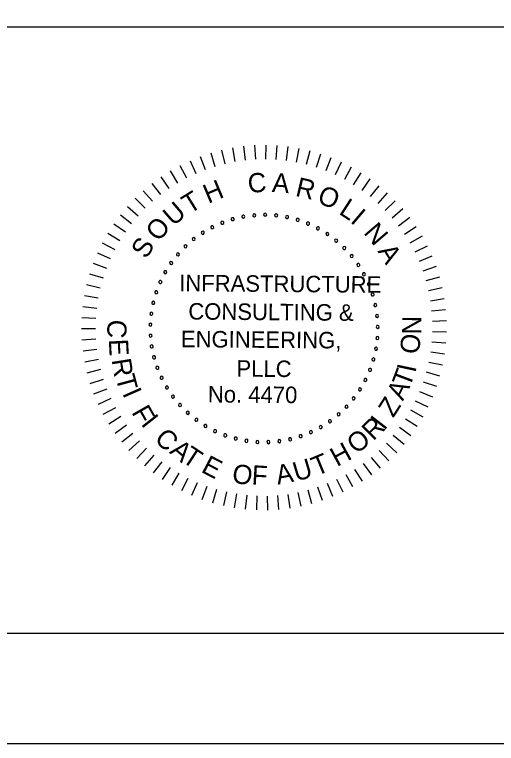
# Model space of a CAD drawing. Extents: x -305 to -161, y -187 to -99.
# Drawn here: x -204.37 to -195.63, y -187.49 to -174.27 of the extents above; entities that cross this region are included whole.
import ezdxf

# ---------------------------------------------------------------- set-up
doc = ezdxf.new("R2010")
doc.units = 0
for name, color, linetype in [('BR_BORDER LINES', 7, 'Continuous'), ('BR_TEXT', 7, 'Continuous'), ('Level 31', 7, 'Continuous')]:
    doc.layers.add(name, color=color, linetype=linetype)

msp = doc.modelspace()

# ---------------------------------------------------------------- linework, layer by layer
at = {"layer": 'BR_BORDER LINES'}
for p, q in [((-214.64, -174.489), (-193.18, -174.489)), ((-297.843, -185.489), (-163.178, -185.489))]:
    msp.add_line(p, q, dxfattribs=at)
at = {"layer": 'BR_TEXT'}
for p, q in [((-200.615, -176.726), (-200.555, -176.974)), ((-200.417, -176.685), (-200.373, -176.936)), ((-200.217, -176.656), (-200.188, -176.909)), ((-200.016, -176.64), (-200.002, -176.894)), ((-199.814, -176.636), (-199.816, -176.89)), ((-199.612, -176.644), (-199.63, -176.898)), ((-199.411, -176.664), (-199.444, -176.917)), ((-199.212, -176.697), (-199.26, -176.947)), ((-199.015, -176.741), (-199.079, -176.988)), ((-201.001, -176.844), (-200.912, -177.082)), ((-200.81, -176.779), (-200.735, -177.023)), ((-198.821, -176.798), (-198.9, -177.04)), ((-198.631, -176.866), (-198.724, -177.103)), ((-201.37, -177.007), (-201.252, -177.233)), ((-201.188, -176.92), (-201.084, -177.153)), ((-198.446, -176.946), (-198.553, -177.177)), ((-201.546, -177.106), (-201.415, -177.324)), ((-198.265, -177.037), (-198.387, -177.261)), ((-198.091, -177.139), (-198.226, -177.355)), ((-201.716, -177.215), (-201.572, -177.425)), ((-197.923, -177.251), (-198.071, -177.458)), ((-201.879, -177.334), (-201.723, -177.535)), ((-197.762, -177.373), (-197.922, -177.571)), ((-202.035, -177.463), (-201.866, -177.654)), ((-197.609, -177.505), (-197.781, -177.693)), ((-202.182, -177.601), (-202.002, -177.781)), ((-197.464, -177.646), (-197.647, -177.823)), ((-202.321, -177.748), (-202.13, -177.917)), ((-197.329, -177.795), (-197.522, -177.961)), ((-202.45, -177.903), (-202.25, -178.06)), ((-202.57, -178.065), (-202.36, -178.21)), ((-197.202, -177.952), (-197.405, -178.106)), ((-197.086, -178.117), (-197.298, -178.258)), ((-202.679, -178.235), (-202.461, -178.366)), ((-196.979, -178.289), (-197.199, -178.417)), ((-202.779, -178.411), (-202.553, -178.529)), ((-196.883, -178.467), (-197.111, -178.581)), ((-202.867, -178.593), (-202.634, -178.696)), ((-196.799, -178.65), (-197.033, -178.75)), ((-202.944, -178.779), (-202.705, -178.869)), ((-196.725, -178.838), (-196.965, -178.924)), ((-203.009, -178.97), (-202.766, -179.045)), ((-196.664, -179.03), (-196.908, -179.101)), ((-203.063, -179.165), (-202.815, -179.225)), ((-196.614, -179.226), (-196.862, -179.282)), ((-203.104, -179.363), (-202.853, -179.407)), ((-196.576, -179.424), (-196.827, -179.465)), ((-203.134, -179.562), (-202.881, -179.592)), ((-196.55, -179.625), (-196.804, -179.65)), ((-203.151, -179.764), (-202.897, -179.777)), ((-196.537, -179.826), (-196.791, -179.836)), ((-203.156, -179.965), (-202.901, -179.964)), ((-196.535, -180.028), (-196.79, -180.022)), ((-203.149, -180.167), (-202.895, -180.15)), ((-196.547, -180.23), (-196.8, -180.208)), ((-203.129, -180.368), (-202.877, -180.335)), ((-196.57, -180.43), (-196.822, -180.393)), ((-203.097, -180.568), (-202.847, -180.52)), ((-196.606, -180.629), (-196.855, -180.577)), ((-203.053, -180.765), (-202.807, -180.701)), ((-196.653, -180.825), (-196.899, -180.758)), ((-202.997, -180.959), (-202.755, -180.881)), ((-196.713, -181.018), (-196.954, -180.936)), ((-202.93, -181.149), (-202.693, -181.056)), ((-196.784, -181.207), (-197.02, -181.111)), ((-202.851, -181.335), (-202.62, -181.228)), ((-196.867, -181.392), (-197.096, -181.281)), ((-202.761, -181.516), (-202.536, -181.395)), ((-196.96, -181.57), (-197.182, -181.446)), ((-202.66, -181.69), (-202.443, -181.556)), ((-197.065, -181.743), (-197.279, -181.605)), ((-202.548, -181.859), (-202.34, -181.711)), ((-197.179, -181.91), (-197.385, -181.759)), ((-202.426, -182.02), (-202.228, -181.86)), ((-197.304, -182.068), (-197.5, -181.905)), ((-202.295, -182.173), (-202.107, -182.002)), ((-202.155, -182.319), (-201.977, -182.136)), ((-197.438, -182.219), (-197.623, -182.045)), ((-202.006, -182.455), (-201.84, -182.262)), ((-197.733, -182.495), (-197.895, -182.3)), ((-197.581, -182.362), (-197.756, -182.176)), ((-201.849, -182.582), (-201.695, -182.379)), ((-197.892, -182.62), (-198.042, -182.414)), ((-201.685, -182.699), (-201.543, -182.487)), ((-198.059, -182.734), (-198.196, -182.519)), ((-201.513, -182.806), (-201.385, -182.586)), ((-201.336, -182.903), (-201.221, -182.675)), ((-198.411, -182.93), (-198.522, -182.701)), ((-198.232, -182.837), (-198.356, -182.615)), ((-201.153, -182.988), (-201.053, -182.754)), ((-200.965, -183.062), (-200.879, -182.822)), ((-198.596, -183.012), (-198.692, -182.777)), ((-200.773, -183.125), (-200.702, -182.88)), ((-200.577, -183.175), (-200.521, -182.927)), ((-200.379, -183.214), (-200.338, -182.962)), ((-199.174, -183.188), (-199.226, -182.939)), ((-198.978, -183.142), (-199.045, -182.896)), ((-198.785, -183.083), (-198.867, -182.842)), ((-200.179, -183.24), (-200.154, -182.987)), ((-199.978, -183.254), (-199.968, -183)), ((-199.776, -183.256), (-199.781, -183.002)), ((-199.574, -183.246), (-199.595, -182.992)), ((-199.373, -183.223), (-199.41, -182.971))]:
    msp.add_line(p, q, dxfattribs=at)
for centre, start, end in [((-200.22, -177.935), 10.6038, 190.6038), ((-200.22, -177.935), 190.6038, 10.6038), ((-200.023, -177.908), 5.0653, 185.0653), ((-200.023, -177.908), 185.0653, 5.0653), ((-199.824, -177.9), 359.5268, 179.5268), ((-199.824, -177.9), 179.5268, 359.5268), ((-199.625, -177.912), 353.9884, 173.9884), ((-199.625, -177.912), 173.9884, 353.9884), ((-199.428, -177.943), 168.4499, 348.4499), ((-199.428, -177.943), 348.4499, 168.4499), ((-200.603, -178.045), 21.6807, 201.6807), ((-200.603, -178.045), 201.6807, 21.6807), ((-200.414, -177.98), 16.1422, 196.1422), ((-200.414, -177.98), 196.1422, 16.1422), ((-199.235, -177.992), 162.9114, 342.9114), ((-199.235, -177.992), 342.9114, 162.9114), ((-199.047, -178.06), 157.373, 337.373), ((-199.047, -178.06), 337.373, 157.373), ((-200.957, -178.226), 32.7576, 212.7576), ((-200.785, -178.127), 27.2191, 207.2191), ((-200.785, -178.127), 207.2191, 27.2191), ((-198.867, -178.146), 151.8345, 331.8345), ((-198.867, -178.146), 331.8345, 151.8345), ((-201.12, -178.341), 38.2961, 218.2961), ((-201.12, -178.341), 218.2961, 38.2961), ((-200.957, -178.226), 212.7576, 32.7576), ((-198.697, -178.249), 146.2961, 326.2961), ((-198.697, -178.249), 326.2961, 146.2961), ((-198.537, -178.368), 320.7576, 140.7576), ((-201.27, -178.472), 43.8345, 223.8345), ((-201.27, -178.472), 223.8345, 43.8345), ((-198.537, -178.368), 140.7576, 320.7576), ((-201.408, -178.617), 49.373, 229.373), ((-201.408, -178.617), 229.373, 49.373), ((-198.389, -178.502), 135.2191, 315.2191), ((-198.389, -178.502), 315.2191, 135.2191), ((-198.255, -178.649), 129.6807, 309.6807), ((-198.255, -178.649), 309.6807, 129.6807), ((-201.53, -178.774), 54.9114, 234.9114), ((-201.53, -178.774), 234.9114, 54.9114), ((-198.135, -178.809), 124.1422, 304.1422), ((-198.135, -178.809), 304.1422, 124.1422), ((-201.637, -178.942), 60.4499, 240.4499), ((-201.637, -178.942), 240.4499, 60.4499), ((-198.032, -178.979), 118.6038, 298.6038), ((-198.032, -178.979), 298.6038, 118.6038), ((-201.727, -179.12), 65.9884, 245.9884), ((-201.727, -179.12), 245.9884, 65.9884), ((-197.945, -179.159), 113.0653, 293.0653), ((-197.945, -179.159), 293.0653, 113.0653), ((-201.8, -179.305), 71.5268, 251.5268), ((-201.8, -179.305), 251.5268, 71.5268), ((-197.876, -179.346), 107.5268, 287.5268), ((-197.876, -179.346), 287.5268, 107.5268), ((-201.854, -179.497), 77.0653, 257.0653), ((-201.854, -179.497), 257.0653, 77.0653), ((-197.826, -179.538), 101.9884, 281.9884), ((-197.826, -179.538), 281.9884, 101.9884), ((-201.89, -179.693), 82.6038, 262.6038), ((-201.89, -179.693), 262.6038, 82.6038), ((-197.795, -179.735), 96.4499, 276.4499), ((-197.795, -179.735), 276.4499, 96.4499), ((-201.906, -179.892), 88.1422, 268.1422), ((-201.906, -179.892), 268.1422, 88.1422), ((-197.782, -179.934), 90.9114, 270.9114), ((-197.782, -179.934), 270.9114, 90.9114), ((-201.904, -180.091), 93.6807, 273.6807), ((-201.904, -180.091), 273.6807, 93.6807), ((-197.789, -180.133), 85.373, 265.373), ((-197.789, -180.133), 265.373, 85.373), ((-201.882, -180.289), 99.2191, 279.2191), ((-201.882, -180.289), 279.2191, 99.2191), ((-197.815, -180.331), 79.8345, 259.8345), ((-197.815, -180.331), 259.8345, 79.8345), ((-201.841, -180.484), 104.7576, 284.7576), ((-201.841, -180.484), 284.7576, 104.7576), ((-197.86, -180.525), 74.2961, 254.2961), ((-197.86, -180.525), 254.2961, 74.2961), ((-201.781, -180.675), 110.2961, 290.2961), ((-201.781, -180.675), 290.2961, 110.2961), ((-197.924, -180.714), 68.7576, 248.7576), ((-197.924, -180.714), 248.7576, 68.7576), ((-201.703, -180.858), 115.8345, 295.8345), ((-201.703, -180.858), 295.8345, 115.8345), ((-198.005, -180.896), 63.2191, 243.2191), ((-198.005, -180.896), 243.2191, 63.2191), ((-201.608, -181.033), 121.373, 301.373), ((-201.608, -181.033), 301.373, 121.373), ((-198.104, -181.069), 57.6807, 237.6807), ((-198.104, -181.069), 237.6807, 57.6807), ((-201.497, -181.199), 126.9114, 306.9114), ((-201.497, -181.199), 306.9114, 126.9114), ((-198.219, -181.232), 52.1422, 232.1422), ((-198.219, -181.232), 232.1422, 52.1422), ((-201.37, -181.352), 132.4499, 312.4499), ((-201.37, -181.352), 312.4499, 132.4499), ((-198.349, -181.383), 46.6038, 226.6038), ((-198.349, -181.383), 226.6038, 46.6038), ((-201.228, -181.493), 137.9884, 317.9884), ((-201.228, -181.493), 317.9884, 137.9884), ((-198.493, -181.521), 41.0653, 221.0653), ((-198.493, -181.521), 221.0653, 41.0653), ((-201.074, -181.619), 143.5268, 323.5268), ((-201.074, -181.619), 323.5268, 143.5268), ((-198.649, -181.644), 35.5268, 215.5268), ((-198.649, -181.644), 215.5268, 35.5268), ((-200.909, -181.73), 149.0653, 329.0653), ((-200.909, -181.73), 329.0653, 149.0653), ((-198.817, -181.752), 29.9884, 209.9884), ((-198.817, -181.752), 209.9884, 29.9884), ((-200.733, -181.825), 154.6038, 334.6038), ((-200.733, -181.825), 334.6038, 154.6038), ((-200.549, -181.902), 160.1422, 340.1422), ((-200.549, -181.902), 340.1422, 160.1422), ((-199.18, -181.916), 18.9114, 198.9114), ((-199.18, -181.916), 198.9114, 18.9114), ((-198.995, -181.842), 24.4499, 204.4499), ((-198.995, -181.842), 204.4499, 24.4499), ((-200.359, -181.961), 165.6807, 345.6807), ((-200.359, -181.961), 345.6807, 165.6807), ((-200.164, -182.001), 171.2191, 351.2191), ((-200.164, -182.001), 351.2191, 171.2191), ((-199.965, -182.022), 176.7576, 356.7576), ((-199.965, -182.022), 356.7576, 176.7576), ((-199.766, -182.024), 2.2961, 182.2961), ((-199.766, -182.024), 182.2961, 2.2961), ((-199.568, -182.007), 7.8345, 187.8345), ((-199.568, -182.007), 187.8345, 7.8345), ((-199.372, -181.971), 13.373, 193.373), ((-199.372, -181.971), 193.373, 13.373)]:
    msp.add_arc(centre, 0.028, start, end, dxfattribs=at)
at = {"layer": 'Level 31'}
msp.add_lwpolyline([(-305.176, -187.489), (-161.176, -187.489), (-161.176, -99.489), (-305.176, -99.489)], close=True, dxfattribs=at)

# ---------------------------------------------------------------- texts
at = {"layer": 'BR_TEXT'}
for s, height, rotation, p in [('C', 0.349, 4.7281, (-200.126, -177.506)), ('A', 0.349, 355.6981, (-199.708, -177.486)), ('H', 0.349, 22.7882, (-200.857, -177.704)), ('R', 0.349, 346.6681, (-199.291, -177.554)), ('O', 0.349, 337.638, (-198.9, -177.673)), ('T', 0.349, 31.8182, (-201.196, -177.894)), ('U', 0.349, 40.8482, (-201.49, -178.119)), ('L', 0.349, 327.108, (-198.504, -177.875)), ('I', 0.349, 319.578, (-198.294, -178.026)), ('O', 0.349, 49.8782, (-201.757, -178.403)), ('N', 0.349, 310.548, (-198.051, -178.23)), ('S', 0.349, 58.9083, (-201.979, -178.715)), ('A', 0.349, 301.5179, (-197.791, -178.559)), ('INFRASTRUCTURE', 0.29909, 359.5268, (-201.385, -179.286)), ('CONSULTING &', 0.29909, 359.5268, (-201.22, -179.8)), ('N', 0.349, 89.2085, (-196.993, -180.074)), ('C', 0.349, 267.025, (-202.679, -179.795)), ('ENGINEERING,', 0.29909, 359.5268, (-201.354, -180.302)), ('E', 0.349, 273.025, (-202.662, -180.161)), ('O', 0.349, 83.2085, (-197.038, -180.44)), ('R', 0.349, 279.025, (-202.61, -180.531)), ('PLLC', 0.2991, 359.5268, (-200.347, -180.836)), ('T', 0.349, 69.3954, (-197.203, -181.047)), ('I', 0.349, 77.9093, (-197.1, -180.777)), ('T', 0.349, 285.025, (-202.541, -180.846)), ('A', 0.349, 63.3954, (-197.326, -181.288)), ('I', 0.349, 293.7713, (-202.422, -181.138)), ('No. 4470', 0.2991, 359.5268, (-200.865, -181.304)), ('Z', 0.349, 57.3954, (-197.501, -181.594)), ('F', 0.349, 299.7713, (-202.257, -181.482)), ('I', 0.349, 308.5268, (-202.089, -181.698)), ('R', 0.349, 44.5268, (-197.863, -182.014)), ('I', 0.349, 52.3339, (-197.665, -181.825)), ('C', 0.349, 314.5268, (-201.851, -181.978)), ('O', 0.349, 38.5268, (-198.169, -182.254)), ('A', 0.349, 320.5268, (-201.575, -182.213)), ('H', 0.349, 28.5268, (-198.522, -182.478)), ('T', 0.349, 326.5268, (-201.357, -182.366)), ('E', 0.349, 332.5268, (-201.003, -182.558)), ('T', 0.349, 22.5268, (-198.894, -182.645)), ('O', 0.349, 350.5268, (-200.442, -182.753)), ('A', 0.349, 10.5268, (-199.597, -182.796)), ('U', 0.349, 16.5268, (-199.261, -182.742)), ('F', 0.349, 356.5268, (-200.076, -182.79))]:
    msp.add_text(s, height=height, rotation=rotation, dxfattribs=at).set_placement(p)

doc.saveas('drawing.dxf')
